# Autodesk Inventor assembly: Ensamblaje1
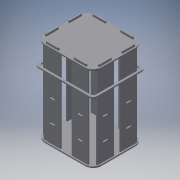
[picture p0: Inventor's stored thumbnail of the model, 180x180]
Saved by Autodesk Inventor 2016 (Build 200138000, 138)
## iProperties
Created: 2016-06
Part Number: Ensamblaje1
Material: Genérico
Document SubType Name: Assembly
Designer: adm
Author: adm
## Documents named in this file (4)
- C:\Users\adm\Desktop\Soportes\Ensamblaje1.iam
- C:\Users\adm\Desktop\Soportes\Pieza1.ipt
- C:\Users\adm\Desktop\Soportes\Soporte 1.ipt
- C:\Users\adm\Desktop\Soportes\Soporte 2.ipt
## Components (12 placed, 3 different names)
1. Pieza1:1 — Coincidencia:1, Coincidencia:2, Coincidencia:3, Coincidencia:4, Coincidencia:5, Coincidencia:6, Coincidencia:7, Coincidencia:8, Coincidencia:9, Coincidencia:10, Coincidencia:11, Coincidencia:12, Coincidencia:13, Coincidencia:14, Coincidencia:15, Coincidencia:16, Coincidencia:17, Coincidencia:18, Coincidencia:19, Coincidencia:20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
2. Pieza1:2 — Coincidencia:25, Coincidencia:26, Coincidencia:27
3. Soporte 1:1 — Coincidencia:4, Coincidencia:5, Coincidencia:6, Coincidencia:28, Coincidencia:29, Coincidencia:30
4. Soporte 1:2 — Coincidencia:13, Coincidencia:14, Coincidencia:15
5. Soporte 1:3 — Coincidencia:10, Coincidencia:11, Coincidencia:12
6. Soporte 1:4 — Coincidencia:7, Coincidencia:8, Coincidencia:9, Coincidencia:27, Coincidencia:32, Coincidencia:33
7. Soporte 1:5 — Coincidencia:1, Coincidencia:2, Coincidencia:3, Coincidencia:26
8. Soporte 1:6 — Coincidencia:22, Coincidencia:23, Coincidencia:24
9. Soporte 1:7 — Coincidencia:16, Coincidencia:17, Coincidencia:18, Coincidencia:25
10. Soporte 1:8 — Coincidencia:19, Coincidencia:20, Coincidencia:21, Coincidencia:31
11. Soporte 2:1 — Coincidencia:28, Coincidencia:29, Coincidencia:30
12. Soporte 2:2 — Coincidencia:31, Coincidencia:32, Coincidencia:33
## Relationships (33: Mate 33)
- Coincidencia:1 [Mate]: Pieza1:1 ↔ Soporte 1:5
- Coincidencia:2 [Mate]: Pieza1:1 ↔ Soporte 1:5
- Coincidencia:3 [Mate]: Pieza1:1 ↔ Soporte 1:5
- Coincidencia:4 [Mate]: Pieza1:1 ↔ Soporte 1:1
- Coincidencia:5 [Mate]: Pieza1:1 ↔ Soporte 1:1
- Coincidencia:6 [Mate]: Pieza1:1 ↔ Soporte 1:1
- Coincidencia:7 [Mate]: Pieza1:1 ↔ Soporte 1:4
- Coincidencia:8 [Mate]: Pieza1:1 ↔ Soporte 1:4
- Coincidencia:9 [Mate]: Pieza1:1 ↔ Soporte 1:4
- Coincidencia:10 [Mate]: Pieza1:1 ↔ Soporte 1:3
- Coincidencia:11 [Mate]: Pieza1:1 ↔ Soporte 1:3
- Coincidencia:12 [Mate]: Pieza1:1 ↔ Soporte 1:3
- Coincidencia:13 [Mate]: Pieza1:1 ↔ Soporte 1:2
- Coincidencia:14 [Mate]: Pieza1:1 ↔ Soporte 1:2
- Coincidencia:15 [Mate]: Pieza1:1 ↔ Soporte 1:2
- Coincidencia:16 [Mate]: Pieza1:1 ↔ Soporte 1:7
- Coincidencia:17 [Mate]: Pieza1:1 ↔ Soporte 1:7
- Coincidencia:18 [Mate]: Pieza1:1 ↔ Soporte 1:7
- Coincidencia:19 [Mate]: Pieza1:1 ↔ Soporte 1:8
- Coincidencia:20 [Mate]: Pieza1:1 ↔ Soporte 1:8
- Coincidencia:21 [Mate]: Pieza1:1 ↔ Soporte 1:8
- Coincidencia:22 [Mate]: Pieza1:1 ↔ Soporte 1:6
- Coincidencia:23 [Mate]: Pieza1:1 ↔ Soporte 1:6
- Coincidencia:24 [Mate]: Pieza1:1 ↔ Soporte 1:6
- Coincidencia:25 [Mate]: Pieza1:2 ↔ Soporte 1:7
- Coincidencia:26 [Mate]: Pieza1:2 ↔ Soporte 1:5
- Coincidencia:27 [Mate]: Pieza1:2 ↔ Soporte 1:4
- Coincidencia:28 [Mate]: Soporte 1:1 ↔ Soporte 2:1
- Coincidencia:29 [Mate]: Soporte 1:1 ↔ Soporte 2:1
- Coincidencia:30 [Mate]: Soporte 1:1 ↔ Soporte 2:1
- Coincidencia:31 [Mate]: Soporte 1:8 ↔ Soporte 2:2
- Coincidencia:32 [Mate]: Soporte 1:4 ↔ Soporte 2:2
- Coincidencia:33 [Mate]: Soporte 1:4 ↔ Soporte 2:2
